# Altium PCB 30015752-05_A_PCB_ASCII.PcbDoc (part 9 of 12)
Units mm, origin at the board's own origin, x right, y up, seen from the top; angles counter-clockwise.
Board outline 100.05 x 72 mm, 10 copper layers (Top, GND_2, Signal_3, Signal_4, PWR_5, GND_6, Signal_7, Signal_8, GND_9, Bottom), stack 1.493 mm thick; 577 components, 546 nets, 2389 pads, 1412 vias.
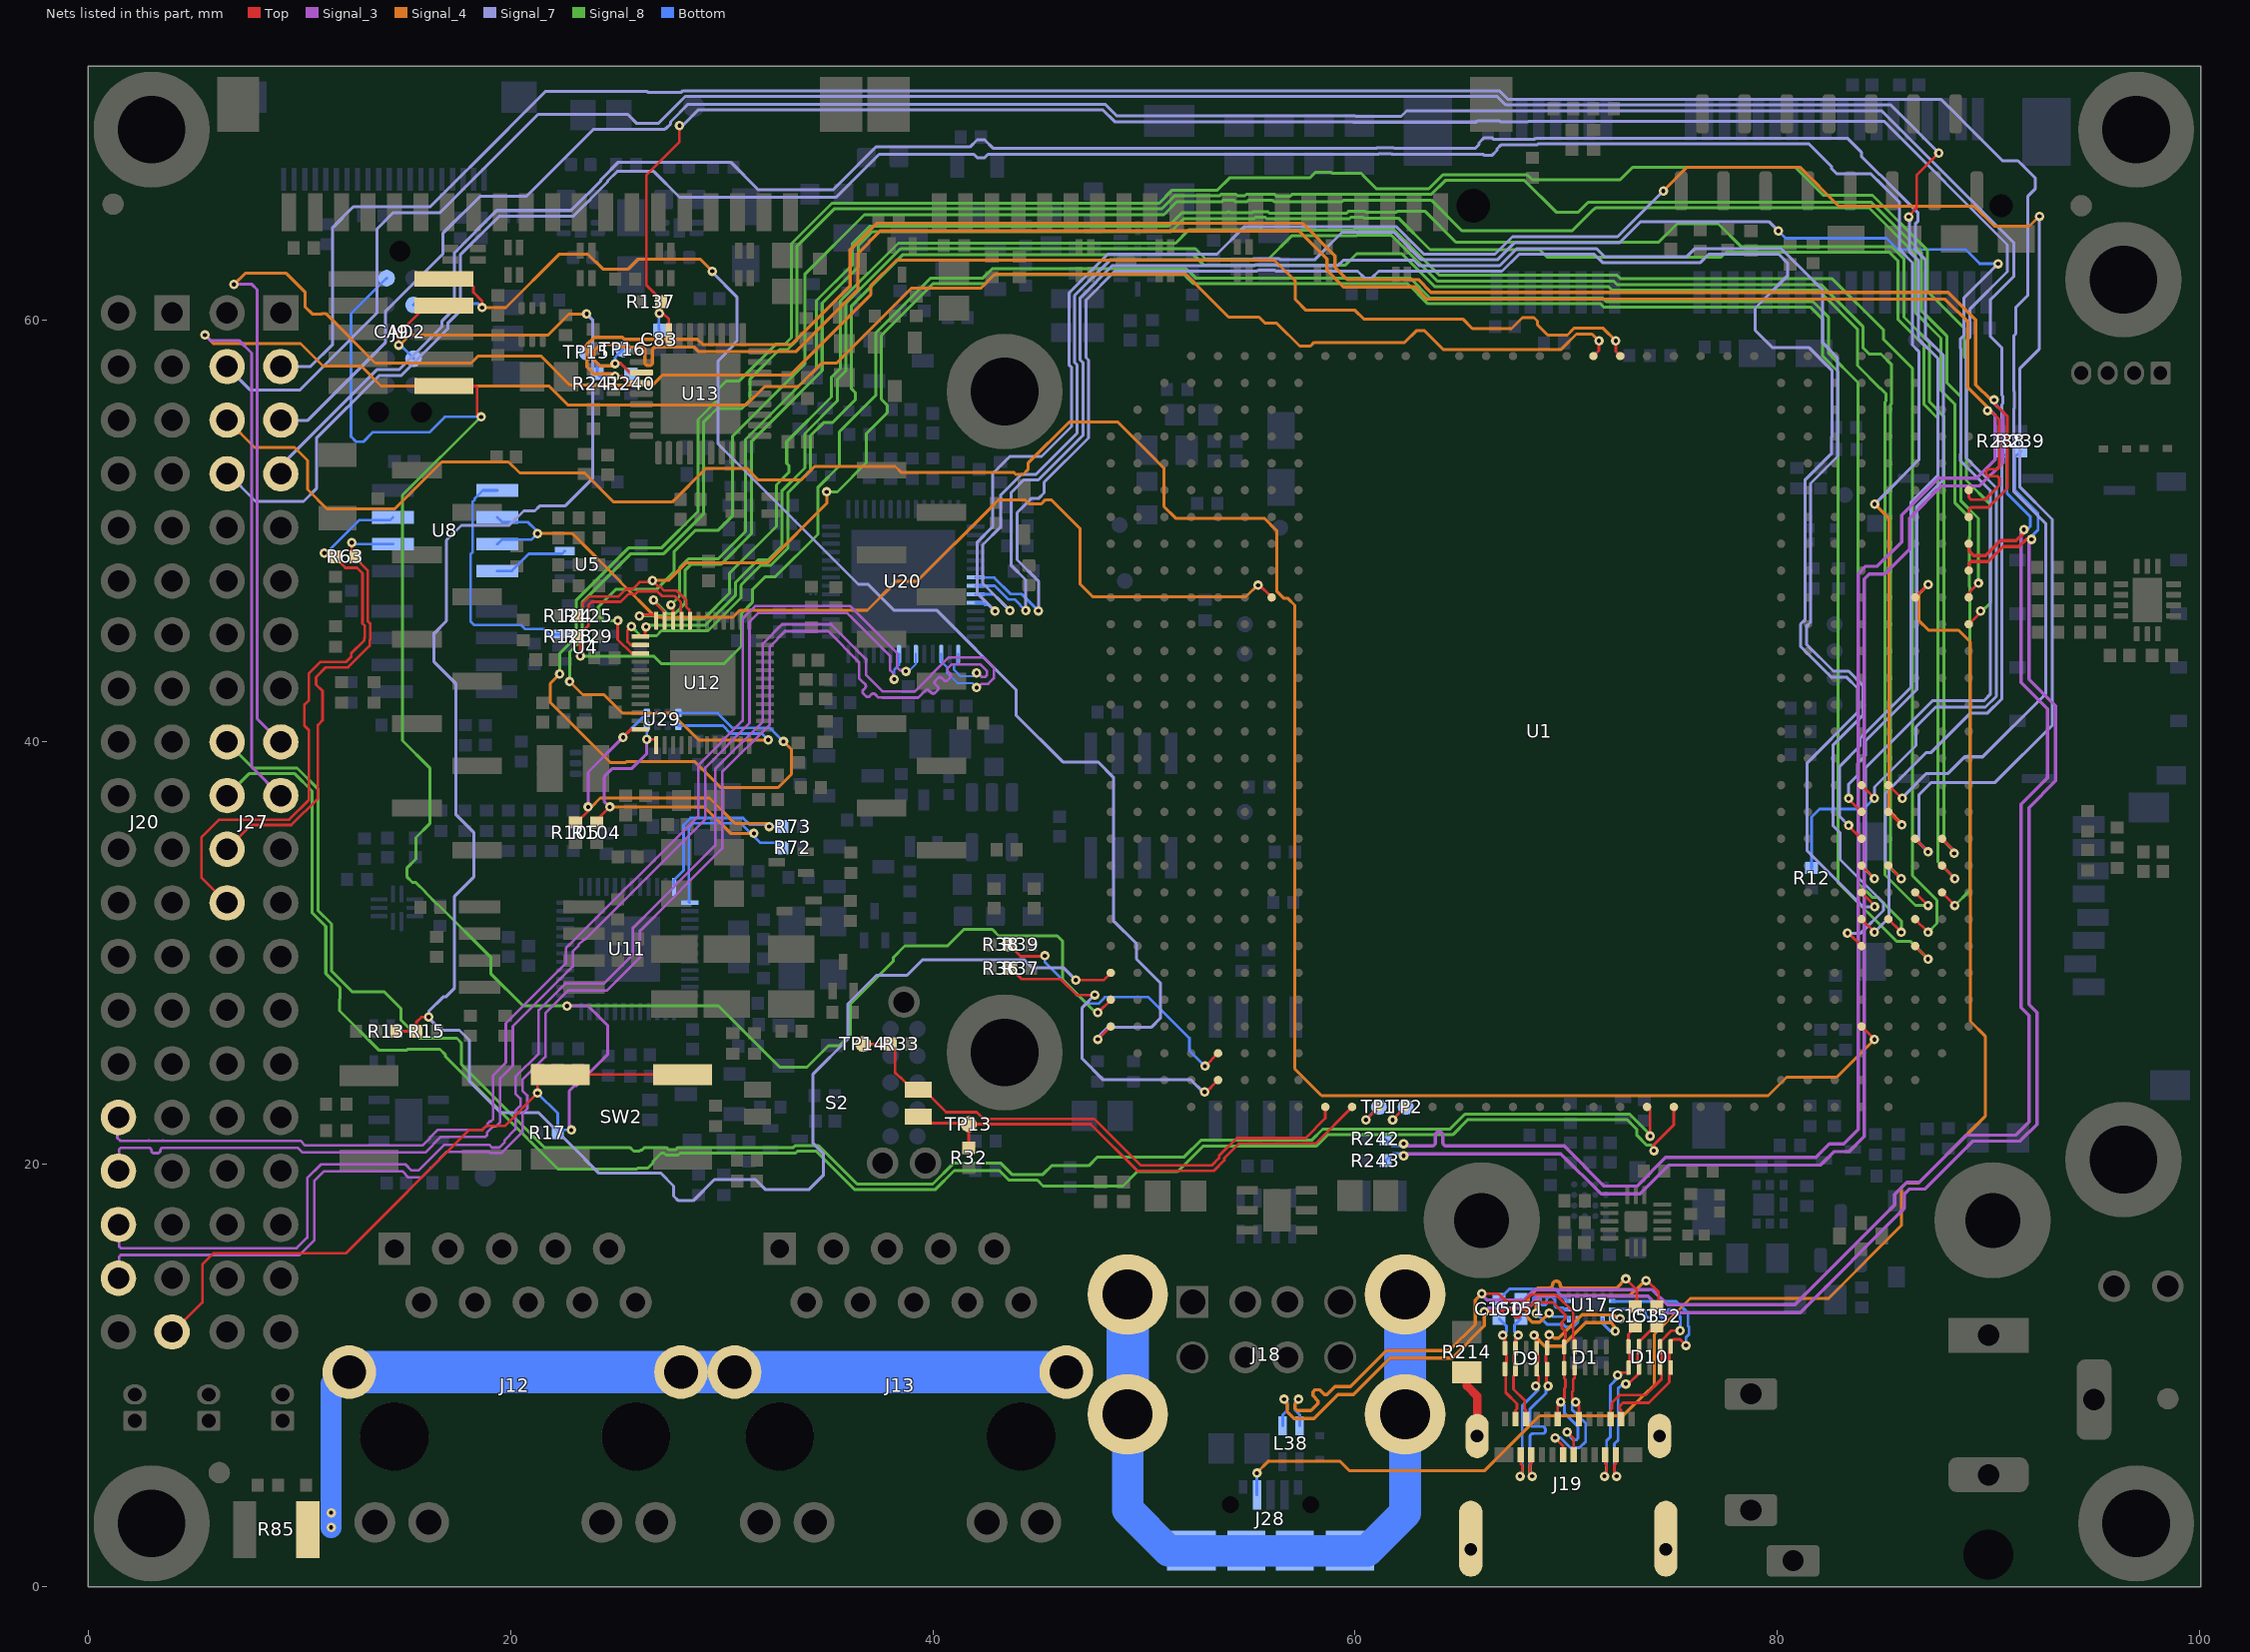
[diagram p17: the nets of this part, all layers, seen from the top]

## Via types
v1: diameter 0.45, hole 0.2, Top to Bottom, tented both sides, 1412 vias

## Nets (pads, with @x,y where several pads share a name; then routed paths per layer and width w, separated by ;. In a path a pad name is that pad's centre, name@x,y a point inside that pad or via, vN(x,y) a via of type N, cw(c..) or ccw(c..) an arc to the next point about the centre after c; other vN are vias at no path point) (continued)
RGMII2_RX_CTL: R124.1 R125.2 U1.C23 U12.32 | length 107
  Top w0.127: R125.2@23.2,46.075 23.275,46.075 23.422,46.221 23.422,46.581 23.74,46.899 25.113,46.899 25.473,47.259 25.797,47.259 26.113,47.575 26.787,47.575 26.968,47.395 27.052,47.395 27.276,47.171 27.876,47.171 28.321,46.726 28.321,46.407 28.464,46.265 28.464,45.786 U12.32@28.5,45.75 ; U1.C23@86.53,30.34 87.14,29.73 v1(87.14,29.72)
  Signal_8 w0.142: v1(34.975,51.85) 35.475,51.85 36.854,53.229 36.854,54.606 37.848,55.6 37.848,55.95 37.562,56.237 37.562,59.261 40.008,61.708 42.487,61.708 42.919,62.14 51.9,62.14 52.332,61.708 62.492,61.708 63.448,60.752 71.625,60.752 71.785,60.592 81.583,60.592 82.15,60.025 82.15,58.275 82.881,57.544 82.881,33.326 85.64,30.567 86.293,30.567 v1(87.14,29.72)
  Signal_4 w0.142: v1(26.726,47.652) 27.473,47.652 28.321,48.5 32.173,48.5 34.975,51.302 v1(34.975,51.85)
RGMII2_RXC: R128.1 R129.2 U1.D22 U12.33 | length 113.2
  Top w0.127: v1(23.3,44.075) 23.3,44.9 R129.2@23.2,45 23.2,45.025 23.685,45.51 23.685,46.485 23.845,46.645 25.218,46.645 25.578,47.005 25.902,47.005 26.037,47.141 26.947,47.141 27.172,46.916 27.772,46.916 28.067,46.621 28.067,45.783 U12.33@28.1,45.75 ; U1.D22@85.26,31.61 85.87,31 v1(85.87,30.99)
  Signal_8 w0.142: v1(23.3,44.075) 26.775,44.075 27.15,43.7 30.1,43.7 30.936,44.536 30.936,46.093 31.452,46.609 31.452,47.212 32.062,47.822 32.536,47.822 34.552,49.837 34.552,52.075 34.575,52.075 35.575,53.075 35.575,54.691 37.292,56.408 37.292,59.372 39.897,61.977 42.375,61.977 42.807,62.409 52.012,62.409 52.443,61.977 62.604,61.977 63.554,61.027 69.176,61.027 69.181,61.022 71.737,61.022 71.897,60.862 81.694,60.862 82.419,60.137 82.419,58.431 83.827,57.023 83.827,33.324 84.52,32.631 84.773,32.631 85.87,31.534 v1(85.87,30.99)
RGMII2_TD0: U1.C22 U12.36 | length 105.6
  Top w0.127: v1(26.1,45.975) 26.15,46.025 26.9,46.025 U12.36@26.9,45.75 ; U1.C22@86.53,31.61 87.14,31 v1(87.14,30.99)
  Signal_8 w0.142: v1(26.1,45.975) 27.144,45.975 27.312,45.808 29.128,45.808 30.375,47.055 30.375,47.999 32.593,50.217 32.593,52.18 33.179,52.766 33.179,53.102 33.079,53.202 33.079,54.225 35.2,56.346 35.2,57.277 35.612,57.688 35.612,60.882 38.36,63.631 51.502,63.631 52.125,64.254 53.761,64.254 55.45,64.254 55.516,64.319 55.529,64.319 55.608,64.24 59.935,64.24 60.016,64.32 60.154,64.32 60.196,64.279 61.825,64.279 64,62.104 72.421,62.104 72.586,61.939 82.611,61.939 85.027,59.523 85.027,59.072 86.4,57.698 86.4,33.672 87.563,32.508 87.563,31.413 v1(87.14,30.99)
RGMII2_TD1: U1.D20 U12.37 | length 101.7
  Top w0.127: U12.37@26.15,45 26.375,45 26.375,45.415 v1(26.42,45.46) ; U1.D20@85.26,34.15 85.87,33.54 v1(85.87,33.53)
  Signal_8 w0.142: v1(26.42,45.46) 26.498,45.538 29.239,45.538 30.644,46.943 30.644,47.546 31.727,48.629 32.202,48.629 32.862,49.29 32.862,51.912 33.937,52.987 33.937,54.617 35.469,56.15 35.469,57.165 35.881,57.577 35.881,60.771 38.472,63.362 52.44,63.362 52.938,62.863 55.888,62.863 56.995,63.97 60.047,63.97 60.078,64.001 61.722,64.001 63.888,61.835 72.231,61.835 72.396,61.669 82.056,61.669 84.066,59.659 84.066,58.659 84.35,58.375 84.911,58.375 85.417,57.869 85.417,56.038 85.369,55.99 85.369,34.031 v1(85.87,33.53)
RGMII2_TD2: U1.C21 U12.38 | length 104.8
  Top w0.127: v1(25.725,45.475) 25.539,45.289 25.539,44.745 25.684,44.6 U12.38@26.15,44.6 ; U1.C21@86.53,32.88 87.14,32.27 v1(87.14,32.26)
  Signal_8 w0.142: v1(25.725,45.475) 26.163,45.037 26.915,45.037 27.148,45.269 29.351,45.269 30.913,46.832 30.913,47.435 31.839,48.36 32.313,48.36 33.132,49.178 33.132,51.801 34.206,52.875 34.206,54.506 34.825,55.125 35.247,55.125 36.325,56.202 36.325,56.553 36.15,56.728 36.15,60.659 38.583,63.092 52.328,63.092 52.827,62.594 59.544,62.594 60.075,63.125 62.217,63.125 63.777,61.565 72.015,61.565 72.181,61.4 81.944,61.4 83.797,59.547 83.797,57.828 84.877,56.748 84.9,56.748 85.148,56.5 85.148,56.15 85.1,56.102 85.1,33.702 86.542,32.26 v1(87.14,32.26)
RGMII2_TD3: U1.B21 U12.39 | length 114.5
  Top w0.127: v1(25.075,45.75) 25.075,44.85 25.725,44.2 U12.39@26.15,44.2 ; U1.B21@87.8,32.88 88.41,32.27 v1(88.41,32.26)
  Signal_8 w0.142: v1(25.075,45.75) 24.4,45.75 24.15,46 24.15,46.4 24.979,47.229 26.902,47.229 27.738,48.066 27.738,49.012 28.742,50.015 29.815,50.015 30.52,50.72 30.52,54.501 33.95,57.931 33.95,62.175 36.752,64.977 50.944,64.977 51.567,65.6 53.701,65.6 53.766,65.665 54.253,65.665 54.319,65.6 54.892,65.6 54.958,65.665 56.086,65.665 56.166,65.586 59.378,65.586 59.459,65.667 63.608,65.667 65.062,64.213 70.283,64.213 71.301,65.232 71.332,65.232 71.4,65.3 84.344,65.3 86.534,63.11 86.534,63.066 86.55,63.05 86.55,60.331 87.752,59.129 87.752,56.656 88.419,55.99 88.419,51.319 89.112,50.625 89.112,49.713 89.102,49.703 89.102,47.35 89.112,47.339 89.112,32.962 v1(88.41,32.26)
RGMII2_TX_CTL: U1.B19 U12.34 | length 104.6
  Top w0.127: v1(27.6,46.5) 27.7,46.4 U12.34@27.7,45.75 ; U1.B19@87.8,35.42 88.41,34.81 88.379,34.779 v1(88.379,34.727)
  Signal_8 w0.142: v1(27.6,46.5) 28.008,46.908 28.008,48.262 28.423,48.677 29.84,48.677 31.132,49.968 31.132,54.336 33.422,56.626 33.422,56.641 34.488,57.708 34.488,60.902 36.2,62.613 36.2,63.625 37.014,64.439 51.167,64.439 51.79,65.061 53.924,65.061 53.989,65.127 54.03,65.127 54.096,65.061 55.116,65.061 55.181,65.127 55.863,65.127 55.943,65.047 59.601,65.047 59.682,65.128 60.489,65.128 60.531,65.086 61.944,65.086 61.986,65.128 63.325,65.128 64.778,63.675 74.378,63.675 75.257,64.553 77.197,64.553 78.281,63.469 85.413,63.469 85.996,62.887 85.996,60.124 87.213,58.906 87.213,56.103 87.88,55.437 87.88,35.33 88.379,34.831 v1(88.379,34.727)
RGMII2_TXC: U1.B20 U12.35 | length 106.5
  Top w0.127: v1(26.775,46.725) 26.775,46.675 27.3,46.15 U12.35@27.3,45.75 ; U1.B20@87.8,34.15 88.41,33.54 v1(88.41,33.53)
  Signal_8 w0.142: v1(26.775,46.725) 27.423,46.077 27.775,46.077 28.277,46.578 28.277,48.15 28.534,48.408 29.952,48.408 31.401,49.857 31.401,54.224 33.691,56.515 33.691,56.53 34.758,57.596 34.758,60.79 36.469,62.502 36.469,63.513 37.125,64.169 51.279,64.169 51.902,64.792 53.984,64.792 55.227,64.792 55.293,64.858 55.752,64.858 55.831,64.778 59.712,64.778 59.793,64.859 60.377,64.859 60.419,64.817 62.048,64.817 63.55,63.315 68.745,63.315 69.092,62.969 77.344,62.969 77.575,63.2 85.301,63.2 85.726,62.775 85.726,60.012 86.944,58.794 86.944,55.992 87.611,55.325 87.611,34.329 v1(88.41,33.53)
RGMII_MDC: U1.A10 U29.5 | length 116.1
  Top w0.127: U1.A10@89.07,46.85 89.07,47.07 v1(89.525,47.525)
  Signal_8 w0.142: v1(22.8,42.86) 22.8,44.275 23.4,44.875 23.4,46.627 25.696,48.923 27.26,48.923 29.15,50.814 29.15,55.169 29.781,55.8 30.95,55.8 31.35,56.2 31.35,57.202 32.731,58.583 33.112,58.583 33.575,59.046 33.575,63.496 35.326,65.246 50.833,65.246 51.455,65.869 53.589,65.869 53.655,65.935 54.365,65.935 54.43,65.869 54.781,65.869 54.847,65.935 56.198,65.935 56.277,65.855 56.93,65.855 57.011,65.936 63.605,65.936 64.269,66.6 68.025,66.6 69.525,65.1 70.575,65.1 71.044,65.569 84.455,65.569 86.819,63.205 86.819,60.442 88.025,59.237 88.025,57.029 88.688,56.366 88.688,51.43 89.525,50.593 v1(89.525,47.525)
  Signal_4 w0.142: v1(22.8,42.86) 23.412,42.248 24.425,42.248 25.3,41.373 27.627,41.373 28.9,40.1 v1(32.2,40.1)
  Bottom w0.127: U29.5@27.95,40.775 30.053,40.775 30.428,40.4 31.9,40.4 v1(32.2,40.1)
RGMII_MDC_3V3: R72.1 R104.1 U11.1 U12.1 U29.8 | length 23.2
  Top w0.127: R104.1@24.075,36.18 24.075,36.3 v1(24.7,36.925) ; v1(26.45,40.125) 26.9,40.125 U12.1@26.9,39.85
  Signal_3 w0.142: v1(24.7,36.925) 24.425,37.2 24.425,38.35 24.825,38.75 25.75,38.75 26.45,39.45 v1(26.45,40.125)
  Signal_4 w0.142: v1(24.7,36.925) 29.175,36.925 30.425,35.675 v1(31.525,35.675)
  Bottom w0.127: v1(26.45,40.125) U29.8@26.45,40.775 ; U11.1@28.49,32.392 28.45,32.432 28.45,35.975 28.625,36.15 30.909,36.15 v1@31.525,35.534 ; v1(31.525,35.675) v1@31.525,35.535 ; R72.1@32.885,34.992 32.885,35.017 32.663,35.239 31.821,35.239 v1@31.525,35.535
RGMII_MDIO: U1.A11 U29.4 | length 125.9
  Top w0.127: U1.A11@89.07,45.58 89.68,46.19 89.668,46.202 v1(89.629,46.202)
  Signal_8 w0.142: v1(22.325,43.225) 22.325,44.2 23.119,44.994 23.119,46.727 25.585,49.192 27.148,49.192 28.881,50.925 28.881,55.281 29.829,56.229 29.829,56.709 30.226,57.106 30.831,57.106 32.577,58.852 33,58.852 33.3,59.152 33.3,63.602 35.214,65.516 50.721,65.516 51.344,66.138 53.478,66.138 54.054,66.715 57.852,66.715 58.121,66.984 58.866,66.984 58.912,66.938 60.287,66.938 60.413,66.812 60.413,66.802 61.01,66.205 63.494,66.205 64.158,66.869 68.152,66.869 68.396,66.625 72.55,66.625 73.148,67.223 80.852,67.223 82.175,65.9 84.505,65.9 87.1,63.305 87.1,61.358 88.85,59.608 88.85,58.25 88.957,58.143 88.957,52.393 90.1,51.25 90.1,46.6 89.702,46.202 v1(89.629,46.202)
  Signal_4 w0.142: v1(22.325,43.225) 21.875,42.775 21.875,41.875 24.723,39.027 25.45,39.027 25.491,39.067 28.737,39.067 29.954,37.85 32.675,37.85 33.298,38.473 33.298,39.652 v1(32.925,40.025)
  Bottom w0.127: U29.4@27.95,41.375 29.812,41.375 30.518,40.669 32.281,40.669 v1(32.925,40.025)
RGMII_MDIO_3V3: R73.1 R105.1 U11.48 U12.48 U29.1 | length 25.1
  Top w0.127: R105.1@23.075,36.18 23.13,36.18 23.675,36.725 v1(23.675,36.925) ; v1(25.327,40.225) v1(25.327,40.225) 25.7,40.6 U12.48@26.15,40.6
  Signal_3 w0.142: v1(23.675,36.925) 23.675,38.575 25.325,40.225 v1(25.327,40.225)
  Signal_4 w0.142: v1(23.675,36.925) 23.825,36.925 24.248,37.348 29.427,37.348 30.625,36.15 32.1,36.15 v1(32.25,36)
  Bottom w0.127: v1(25.327,40.225) 25.327,40.245 25.325,40.247 26.243,41.166 26.29,41.166 26.45,41.325 U29.1@26.45,41.375 ; U11.48@27.74,33.142 27.74,33.462 28.196,33.918 28.196,36.08 28.52,36.404 31.015,36.404 31.328,36.091 32.159,36.091 v1(32.25,36) 32.877,36 R73.1@32.885,35.992
RS485_A: J27.22 R63.1 U8.6 | length 21.7
  Top w0.127: J27.22@6.56,34.92 7.711,36.071 9.612,36.071 10.871,37.33 10.871,40.808 11.091,41.028 11.091,42.422 10.784,42.728 10.784,43.072 11.249,43.536 12.299,43.536 13.328,44.565 13.328,44.822 13.349,44.842 13.349,45.608 13.242,45.714 13.242,48.108 12.475,48.875 v1(12.475,49.45)
  Bottom w0.127: v1(12.475,49.45) 12.55,49.375 U8.6@14.43,49.375
RS485_B: J27.24 R63.2 U8.7 | length 28.6
  Top w0.127: J27.24@6.56,32.38 5.354,33.586 5.354,35.479 6.2,36.325 9.507,36.325 10.445,37.262 10.445,40.557 10.235,40.766 10.235,41.774 10.446,41.985 10.446,43.255 10.981,43.79 12.194,43.79 12.454,44.051 12.454,44.205 13.074,44.825 13.074,44.927 13.095,44.948 13.095,45.502 12.988,45.609 12.988,47.987 12.725,48.25 12.175,48.25 R63.2@11.695,48.73 ; v1(11.176,48.952) 11.473,48.952 R63.2@11.695,48.73 ; R63.2@11.695,48.775 R63.2@11.695,48.73 ; R63.2@11.825,48.525 11.695,48.655 R63.2@11.695,48.73
  Bottom w0.127: v1(11.176,48.952) 11.277,48.952 12.83,50.505 14.29,50.505 U8.7@14.43,50.645
RS485_RE#/DE: U1.AG10 U8.2 U8.3 | length 47.3
  Top w0.127: v1(55.403,47.427) 55.407,47.427 55.44,47.46 U1.AG10@56.05,46.85
  Signal_4 w0.142: v1(21.275,49.875) 22.928,49.875 25.217,47.587 25.217,47.565 26.862,45.92 30.54,45.92 30.86,46.24 36.9,46.24 38.28,47.62 39.268,47.62 42.723,51.075 42.723,51.083 43.115,51.475 44.366,51.475 44.563,51.278 45.137,51.278 45.334,51.475 45.6,51.475 46.98,50.095 46.98,47.47 47.575,46.875 54.829,46.875 55.403,47.449 v1(55.403,47.427)
  Bottom w0.127: U8.3@19.37,49.375 19.579,49.584 20.978,49.584 21.268,49.875 v1(21.275,49.875) 21.213,49.937 21.213,50.024 20.822,50.415 19.599,50.415 U8.2@19.37,50.645
SAI0_RXD: U1.E21 U20.7 | length 94.7
  Top w0.127: U1.E21@83.99,32.88 84.604,32.266 v1(84.604,32.202)
  Signal_7 w0.142: v1(45,46.213) 45,47.62 43.991,48.629 43.991,50.863 44.675,51.547 45.025,51.547 45.273,51.795 45.273,52.304 47.375,54.406 47.375,58.087 47.254,58.207 47.254,60.929 48.623,62.298 55.354,62.298 55.406,62.35 56.194,62.35 56.246,62.298 60.129,62.298 60.45,61.977 60.8,61.977 61.12,62.297 66.964,62.297 67.765,63.098 71.331,63.098 71.719,62.71 76.36,62.71 76.753,63.103 80.07,63.103 80.5,62.673 80.5,62.1 78.95,60.55 78.95,59.5 79.775,58.675 81.512,58.675 82.587,57.6 82.587,54.473 82.58,54.467 82.58,53.68 81.306,52.406 81.306,45.784 81.108,45.587 81.108,44.522 82.547,43.083 83.272,43.083 83.802,42.552 83.802,41.401 81.4,38.999 81.4,34.862 84.06,32.202 v1(84.604,32.202)
  Bottom w0.127: U20.7@42.03,47.8 42.045,47.784 42.903,47.784 43.678,47.009 44.203,47.009 v1(45,46.213)
SAI0_TXC: U1.E23 U20.8 | length 93.8
  Top w0.127: v1(83.325,30.95) 83.38,30.95 U1.E23@83.99,30.34
  Signal_7 w0.142: v1(44.4,46.225) 44.4,47.68 43.722,48.358 43.722,51.821 44.311,52.41 44.999,52.41 47.106,54.517 47.106,57.975 46.985,58.096 46.985,61.041 48.512,62.567 55.243,62.567 55.295,62.619 56.305,62.619 56.357,62.567 59.189,62.567 59.447,62.825 62.776,62.825 63.035,62.566 66.853,62.566 67.654,63.367 71.442,63.367 71.831,62.979 75.704,62.979 76.097,63.372 80.182,63.372 82.15,61.404 82.15,58.902 82.856,58.196 82.856,54.362 82.849,54.355 82.849,53.524 81.575,52.25 81.575,45.672 81.378,45.475 81.378,44.633 82.659,43.352 83.383,43.352 84.071,42.664 84.071,41.289 82.65,39.868 82.65,36.027 82.969,35.708 82.969,34.435 85.027,32.377 85.027,32.026 83.951,30.95 v1(83.325,30.95)
  Bottom w0.127: U20.8@42.03,47.4 42.928,47.4 43.573,46.755 43.87,46.755 v1(44.4,46.225)
SAI0_TXD: U1.E20 U20.9 | length 102.2
  Top w0.127: U1.E20@83.99,34.15 84.6,33.54 v1(84.6,33.53)
  Signal_7 w0.142: v1(43.65,46.225) 42.36,47.515 42.36,49.34 43.22,50.2 43.22,51.7 44.2,52.679 44.887,52.679 46.837,54.629 46.837,57.864 46.716,57.984 46.716,61.152 48.4,62.837 55.131,62.837 55.183,62.889 56.417,62.889 56.469,62.837 58.084,62.837 59.396,64.148 61.833,64.148 63.146,62.835 66.741,62.835 67.565,63.66 72.54,63.66 73.521,64.64 79.167,64.64 79.179,64.651 79.6,64.651 v1(80.051,64.201) ; v1(84.6,33.53) 84.177,33.953 84.177,38.785 87.346,41.954 89.78,41.954 90.102,42.277 90.102,51.894 88.681,53.315 88.681,53.654 88.688,53.662 88.688,58.628 88.681,58.636 88.681,59.102 88.843,59.265 88.843,61.043 90.453,62.653 v1(90.454,62.653)
  Bottom w0.127: U20.9@42.03,47 42.875,47 v1(43.65,46.225) ; v1(80.051,64.201) 80.392,63.859 85.166,63.859 85.694,63.331 88.906,63.331 89.585,62.653 v1(90.454,62.653)
SAI0_TXFS: U1.C19 U20.10 | length 106.8
  Top w0.127: U1.C19@86.53,35.42 87.14,34.81 v1(87.14,34.8)
  Signal_4 w0.142: v1(74.6,66.1) 75.726,67.226 81.067,67.226 82.918,65.375 89.325,65.375 90.275,64.425 91.932,64.425 92.407,64.9 v1(92.425,64.9)
  Signal_7 w0.142: v1(42.95,46.2) 42.091,47.059 42.091,49.452 42.84,50.201 42.84,52.715 43.651,53.526 44.277,53.526 ; 44.278,53.525 45.15,53.525 46.567,54.942 46.567,57.752 46.446,57.873 46.446,61.264 48.289,63.106 53.45,63.106 54.762,64.417 61.945,64.417 63.258,63.105 66.629,63.105 67.454,63.929 72.429,63.929 v1(74.6,66.1) ; v1(87.14,34.8) 86.708,35.232 86.708,37.507 87.275,38.073 90.298,38.073 93.02,40.795 93.02,50.55 91.475,52.095 91.475,55.674 91.495,55.694 91.495,56.714 91.475,56.733 91.475,57.675 92.4,58.6 92.4,64.875 v1(92.425,64.9)
  Bottom w0.127: U20.10@42.03,46.6 42.36,46.6 42.469,46.49 42.653,46.49 42.943,46.2 v1(42.95,46.2)
SCU_BOOT_MODE0: R33.2 S2.2 TP14.1 U1.AE29 | length 26.5
  Top w0.127: TP14.1@36.7,25.7 R33.2@38.02,25.7 38.209,25.511 38.209,24.353 38.46,24.102 38.488,24.102 39.055,23.535 S2.2@39.31,23.535 39.565,23.535 40.629,22.471 42.07,22.471 42.388,22.154 47.646,22.154 49.854,19.946 53.205,19.946 53.555,20.296 53.555,20.402 54.399,21.246 57.659,21.246 58.59,22.177 U1.AE29@58.59,22.72
SCU_BOOT_MODE1: R32.1 S2.1 TP13.1 U1.AD29 | length 24.1
  Top w0.127: S2.1@39.31,22.265 39.626,21.949 41.651,21.949 TP13.1@41.7,21.9 ; R32.1@41.7,20.78 TP13.1@41.7,21.9 ; U1.AD29@59.86,22.72 58.132,20.992 54.504,20.992 53.809,20.297 53.809,20.191 53.31,19.692 49.685,19.692 47.477,21.9 TP13.1@41.7,21.9
SCU_BOOT_MODE2: R36.2 R37.2 U1.AJ28 | length 15.2
  Top w0.127: R37.2@43.7,29.275 44.2,28.775 46.05,28.775 46.8,28.025 v1(47.675,28.025) ; v1(52.878,23.426) 52.878,23.358 U1.AJ28@53.51,23.99
  Signal_7 w0.142: v1(47.675,28.025) 47.075,27.425 47.075,25 48.075,24 52.225,24 52.799,23.426 v1(52.878,23.426)
SCU_BOOT_MODE3: R38.2 R39.2 U1.AJ27 | length 13.3
  Top w0.127: R38.2@43.7,30.4 43.7,30.3 44.15,29.85 45.276,29.85 v1(45.302,29.876) ; v1(52.89,24.65) 52.9,24.65 U1.AJ27@53.51,25.26
  Bottom w0.127: v1(45.302,29.876) 45.302,29.602 45.3,29.6 47.29,27.61 47.847,27.61 48.156,27.918 50.21,27.918 52.15,25.978 52.15,25.39 v1(52.89,24.65)
SCU_UART_RX: TP1.1 U1.AC29 | length 1.7
  Top w0.127: v1(60.51,22.11) 60.52,22.11 U1.AC29@61.13,22.72
  Bottom w0.127: v1(60.51,22.11) 60.515,22.11 61.125,22.72 TP1.1@61.13,22.72
SCU_UART_TX: TP2.1 U1.AB29 | length 1.7
  Top w0.127: v1(61.78,22.11) 61.79,22.11 U1.AB29@62.4,22.72
  Bottom w0.127: v1(61.78,22.11) 61.785,22.11 62.395,22.72 TP2.1@62.4,22.72
SHLD: J12.SHLD1 J12.SHLD2 J13.SHLD1 J13.SHLD2 J18.SH1 J18.SH2 J18.SH3 J18.SH4 J28.6 J28.7 J28.8 J28.9 R85.2 | length 77.1
  Bottom w1: v1(11.5,2.8) v1(11.5,3.5) 11.5,9.6 11.85,9.95 11.85,10.163 J12.SHLD1@12.361,10.163 J12.SHLD1@12.469,10.163
  Bottom w1.5: J18.SH1@49.231,8.155 49.231,3.644 51.175,1.7 J28.9@52.25,1.7 J28.8@54.85,1.7 J28.7@57.15,1.7 J28.6@59.75,1.7 60.575,1.7 62.371,3.496 J18.SH3@62.371,8.155
  Bottom w2: J12.SHLD1@12.469,10.163 J12.SHLD2@28.071,10.163 J13.SHLD1@30.611,10.163 J13.SHLD2@46.213,10.163 ; J18.SH1@49.231,8.155 J18.SH2@49.231,13.835 ; J18.SH3@62.371,8.155 J18.SH4@62.371,13.835
SPI0_CS0: J27.4 U1.E19 | length 127.2
  Top w0.127: v1(83.379,36.052) 83.362,36.052 83.36,36.05 U1.E19@83.99,35.42 ; v1(86.229,64.878) 86.229,64.929 86.6,65.3 86.6,66.85 v1(87.65,67.9)
  Signal_7 w0.142: J27.4@6.56,57.78 7.658,56.682 10.032,56.682 13.675,60.325 13.675,64.3 14.45,65.075 16.654,65.075 21.302,69.723 25.552,69.723 25.983,69.292 26.992,69.292 28.277,70.577 66.733,70.577 67.143,70.167 85.383,70.167 v1(87.65,67.9) ; v1(83.379,36.052) 82.956,36.475 82.956,38.855 83.908,39.807 83.908,40.167 86.333,42.592 86.333,51.375 87.604,52.646 87.604,54.1 87.606,54.102 87.606,58.169 86.675,59.1 86.675,62.806 86.268,63.213 86.268,64.651 86.33,64.714 86.33,64.777 v1(86.229,64.878)
SPI0_CS1: J27.6 U1.E26 | length 115.6
  Top w0.127: U1.E26@83.99,26.53 84.6,25.92 v1(84.6,25.91)
  Signal_4 w0.142: J27.6@6.56,55.24 J27.6@6.585,55.24 ; J27.6@6.575,55.245 6.58,55.245 J27.6@6.585,55.24 ; v1(84.6,25.91) 82.815,24.125 80.445,24.125 79.569,23.249 58.418,23.249 58.374,23.292 57.145,24.521 57.145,46.48 56.825,46.8 56.635,46.8 56.287,47.148 56.287,50.013 55.7,50.6 51.5,50.6 50.95,51.15 50.95,52.975 48.775,55.15 46.45,55.15 44.525,53.225 44.525,52.927 44.277,52.679 43.927,52.679 43.831,52.775 38.5,52.775 38.225,53.05 34.4,53.05 33.754,52.404 31.746,52.404 31.183,52.967 29.261,52.967 27.658,51.363 24.879,51.363 23.5,52.742 20.433,52.742 19.904,53.271 16.736,53.271 14.5,51.035 11.311,51.035 10.386,51.96 10.386,53.339 9.775,53.95 7.875,53.95 J27.6@6.585,55.24
SPI0_IRQ_N: J27.8 U1.D18 | length 124.5
  Top w0.127: v1@84.6,51.27 v1(84.61,51.27) ; U1.D18@85.26,36.69 85.875,36.075 85.877,36.077 v1(85.904,36.077)
  Signal_4 w0.142: v1(84.61,51.27) 85.3,50.58 85.3,36.75 85.904,36.146 v1(85.904,36.077)
  Signal_7 w0.142: J27.8@6.575,52.705 6.62,52.705 7.925,51.4 10.2,51.4 10.802,52.002 10.802,54.39 13.773,57.362 14.823,57.362 17.023,59.562 17.023,59.833 17.613,60.423 17.613,63.069 19.45,64.906 22.977,64.906 24.604,66.533 24.604,66.579 25.048,67.023 26.787,67.023 28.007,65.803 35.418,65.803 37.456,67.84 41.942,67.84 42.102,67.68 42.452,67.68 42.612,67.84 61.111,67.84 61.141,67.871 61.715,67.871 61.757,67.829 66.073,67.829 66.125,67.777 66.475,67.777 66.723,68.025 66.723,68.098 66.904,68.279 68.618,68.279 68.67,68.331 81.494,68.331 82.581,67.244 82.581,67.153 82.829,66.905 84.436,66.905 84.746,66.594 84.758,66.594 85.794,65.558 85.794,63.306 86.4,62.7 86.4,58.8 86.7,58.5 86.7,53.36 v1(84.61,51.27)
SPI0_SCK: J27.3 U1.D17 | length 128.9
  Top w0.127: U1.D17@85.26,37.96 85.88,37.34 v1(85.922,37.34)
  Signal_7 w0.142: J27.3@9.1,57.78 10.52,57.78 11.575,58.835 11.575,64.375 12.555,65.355 16.195,65.355 17.917,67.077 17.925,67.077 18.173,67.325 18.173,67.333 21.663,70.823 26.45,70.823 26.498,70.775 28.094,70.775 28.165,70.846 66.844,70.846 67.254,70.436 87.759,70.436 90.666,67.529 91.402,67.529 92.231,66.7 92.231,66.216 91.875,65.86 91.875,61.166 91.3,60.591 91.3,59.335 91.206,59.24 91.206,56.622 91.225,56.602 91.225,55.805 91.206,55.786 91.206,51.855 92.711,50.35 92.711,42.286 89.725,39.3 88.875,39.3 88.089,38.514 87.061,38.514 85.886,37.34 v1(85.922,37.34)
SPI0_SDI: J27.5 U1.E22 | length 130.2
  Top w0.127: U1.E22@83.99,31.61 84.6,31 v1(84.6,30.995)
  Signal_7 w0.142: J27.5@9.1,55.24 10.396,55.24 14.065,58.91 14.065,60.385 16.806,63.125 16.806,64.106 18.55,65.85 20.75,65.85 23.923,69.023 27.3,69.023 27.325,69.048 27.352,69.048 27.577,69.273 27.577,69.375 28.411,70.21 48.162,70.21 48.723,69.648 60.01,69.648 60.028,69.63 62.18,69.63 62.447,69.897 84.941,69.897 91.2,63.639 91.2,62.05 90.1,60.95 90.1,59.2 90.641,58.659 90.641,56.425 90.687,56.379 90.687,56.029 90.641,55.983 90.641,42.054 89.962,41.375 89.16,41.375 87.294,39.509 87.06,39.509 85.125,37.574 85.125,34.3 85.296,34.129 85.296,31.691 v1(84.6,30.995)
SPI0_SDO: J27.7 U1.E18 | length 120.3
  Top w0.127: v1(83.379,37.327) 83.357,37.327 83.355,37.325 U1.E18@83.99,36.69
  Signal_7 w0.142: J27.7@9.115,52.705 9.115,53.084 13.662,57.631 14.712,57.631 16.754,59.673 16.754,59.944 17.344,60.535 17.344,63.181 19.338,65.175 22.865,65.175 24.275,66.585 24.275,66.625 24.335,66.685 24.335,66.69 25.108,67.463 30.425,67.463 31.738,66.15 35.271,66.15 37.3,68.179 41.754,68.179 42.102,68.526 42.452,68.526 42.852,68.127 61.017,68.127 61.03,68.14 61.826,68.14 61.839,68.127 65.702,68.127 65.877,68.302 65.877,68.375 66.125,68.623 66.475,68.623 66.547,68.551 68.51,68.551 68.559,68.6 83.32,68.6 83.98,67.94 83.98,67.742 84.858,66.864 84.869,66.864 86.652,65.081 86.652,64.655 86.537,64.54 86.537,63.325 87.025,62.837 87.025,59.15 87.875,58.299 87.875,53.99 87.873,53.988 87.873,52.423 86.602,51.152 86.602,42.481 84.177,40.055 84.177,39.357 83.802,38.982 83.802,38.427 83.379,38.004 v1(83.379,37.327)
SPKL_N: J20.34 U20.22 | length 58.9
  Signal_3 w0.124: J20.34@1.46,19.68 1.46,19.685 1.46,20.712 1.533,20.785 2.35,20.785 2.562,20.785 2.859,20.785 cw(c2.859,20.658) 2.987,20.658 ccw(c3.114,20.658) 3.114,20.53 3.284,20.53 ccw(c3.284,20.658) 3.411,20.658 cw(c3.538,20.658) 3.538,20.785 3.55,20.785 9.915,20.785 10.138,20.562 15.962,20.562 16.706,21.306 18.808,21.306 18.886,21.383 18.886,21.494 19.166,21.774 19.166,21.789 19.292,21.789 19.505,22.002 19.505,24.08 20.105,24.68 20.105,26.53 22.95,29.375 22.95,30.083 23.211,30.344 23.211,30.397 23.453,30.639 23.506,30.639 29.225,36.358 29.225,38.8 31.319,40.894 31.319,45.699 31.739,46.119 35.931,46.119 37.975,44.075 37.975,43.404 38.123,43.256 38.123,43.027 v1(38.175,42.975)
  Bottom w0.102: v1(38.175,42.975) 38.175,43.425 38.4,43.65 U20.22@38.4,44.17
SPKL_P: J20.32 U20.20 | length 58.9
  Signal_3 w0.124: J20.32@1.46,22.22 1.445,22.205 1.375,22.135 1.375,21.25 1.51,21.115 2.795,21.115 2.853,21.115 2.859,21.122 2.859,21.124 2.868,21.116 2.873,21.121 2.878,21.115 2.882,21.115 2.886,21.119 2.889,21.115 2.981,21.115 3.417,21.115 3.509,21.115 3.512,21.119 3.515,21.115 3.52,21.115 3.525,21.121 3.53,21.116 3.538,21.124 3.538,21.122 3.545,21.115 3.602,21.115 ; 3.603,21.115 10.052,21.115 10.275,20.892 15.817,20.892 16.561,21.636 18.672,21.636 18.914,21.878 18.914,21.931 19.024,22.041 19.077,22.041 19.175,22.139 19.175,24.217 19.775,24.817 19.775,26.675 22.62,29.52 22.62,30.22 28.895,36.495 28.895,38.92 30.989,41.014 30.989,45.836 31.602,46.449 36.076,46.449 38.305,44.22 38.305,43.541 38.444,43.402 38.673,43.402 v1(38.725,43.35)
  Bottom w0.102: v1(38.725,43.35) 38.85,43.35 39.2,43.7 U20.20@39.2,44.17
SPKR_N: J20.38 U20.15 | length 71.3
  Signal_3 w0.124: J20.38@1.46,14.6 1.46,14.605 1.46,15.632 1.533,15.705 10.005,15.705 10.7,16.4 10.7,19.201 11.168,19.67 14.877,19.67 15.167,19.381 15.783,19.381 16.219,19.817 16.219,19.834 16.98,20.595 18.966,20.595 19.019,20.541 19.571,20.541 19.625,20.595 19.637,20.595 20.563,21.521 20.563,22.41 20.794,22.642 20.794,23.258 20.563,23.49 20.563,24.013 21.65,25.1 21.65,27.158 22.717,28.225 24.549,28.225 26.13,29.807 26.13,31.063 30.025,34.958 30.025,38.575 32.275,40.825 32.275,44.525 33,45.25 35.044,45.25 36.506,43.788 36.506,43.027 36.739,42.794 36.793,42.74 cw(c36.703,42.65) 36.793,42.56 36.707,42.474 ccw(c36.797,42.384) 36.707,42.294 36.827,42.174 ccw(c36.917,42.264) 37.007,42.174 37.093,42.26 cw(c37.183,42.17) 37.273,42.26 37.333,42.2 37.419,42.114 37.612,42.114 37.626,42.1 39.308,42.1 39.55,42.342 39.643,42.434 cw(c39.733,42.344) 39.823,42.434 39.926,42.332 ccw(c40.016,42.422) 40.106,42.332 40.226,42.452 ccw(c40.136,42.542) 40.226,42.632 40.123,42.735 cw(c40.213,42.825) 40.123,42.915 40.243,43.035 cw(c40.333,42.945) 40.423,43.035 40.526,42.932 ccw(c40.616,43.022) 40.706,42.932 40.826,43.052 ccw(c40.736,43.142) 40.826,43.232 40.723,43.335 cw(c40.813,43.425) 40.723,43.515 40.783,43.575 40.891,43.683 42.247,43.683 42.555,43.374 42.555,43.163 42.482,43.09 42.311,43.09 42.132,43.269 v1(42.075,43.269)
  Bottom w0.102: U20.15@41.2,44.17 41.2,43.8 41,43.6 41,43.425 41.3,43.125 41.932,43.125 v1(42.075,43.269)
SPKR_P: J20.36 U20.17 | length 71.5
  Signal_3 w0.124: J20.36@1.46,17.14 1.46,16.108 1.533,16.035 9.868,16.035 10.37,16.537 10.37,19.338 11.032,20 15.014,20 15.303,19.711 15.647,19.711 16.861,20.925 18.991,20.925 19.124,20.792 19.467,20.792 19.709,21.035 19.709,21.134 20.233,21.658 20.233,22.547 20.464,22.778 20.464,23.122 20.233,23.353 20.233,24.15 21.325,25.242 21.325,27.3 22.58,28.555 24.412,28.555 25.8,29.943 25.8,31.2 29.695,35.095 29.695,38.712 31.945,40.962 31.945,44.662 32.863,45.58 35.181,45.58 36.837,43.925 36.837,43.183 37.628,42.392 39.134,42.392 40.754,44.013 42.383,44.013 42.886,43.511 42.886,43.026 42.619,42.76 42.311,42.76 42.132,42.582 v1(42.075,42.582)
  Bottom w0.102: U20.17@40.4,44.17 40.4,43.818 40.575,43.643 40.67,43.548 40.67,43.288 41.163,42.795 41.862,42.795 v1(42.075,42.582)
SS3_1_RX_N: D9.1 D9.10 J19.B10 U17.1 | length 14
  Top w0.132: J19.B10@68.35,6.24 68.35,5.824 68.284,5.758 68.284,5.329 v1(68.389,5.225) ; D9.1@69.1,11.3 69.056,11.256 69.056,10.963 69.034,10.941 69.034,10.661 69.056,10.639 69.056,10.3 69.056,10.099 69.1,10.055 69.068,10.023 69.068,9.736 69.078,9.727 69.078,9.561 v1(69.139,9.5) ; D9.1@69.1,11.305 69.144,11.349 69.144,11.869 v1(69.2,11.925)
  Signal_4 w0.157: v1(69.2,11.925) 69.276,11.925 69.439,11.763 69.647,11.763 70.758,12.874 71.456,12.874 71.464,12.866 72.269,12.866 72.405,12.731 72.55,12.731 72.594,12.731 72.563,12.7 v1(72.55,12.7)
  Bottom w0.132: v1(68.389,5.225) 68.284,5.329 68.284,6.75 68.284,6.916 68.284,7.099 cw(c68.434,7.099) 68.434,7.248 68.874,7.248 ccw(c68.874,7.398) 69.024,7.398 69.024,7.431 ccw(c68.874,7.431) 68.874,7.58 68.434,7.58 cw(c68.434,7.73) 68.284,7.73 68.284,7.775 68.284,8.409 69.034,9.159 69.034,9.31 69.139,9.414 v1(69.139,9.5) ; U17.1@72.125,12.675 72.15,12.7 v1(72.55,12.7)
SS3_1_RX_P: D9.2 D9.9 J19.B11 U17.2 | length 14.1
  Top w0.132: v1(67.812,5.225) 67.916,5.329 67.916,5.758 67.85,5.824 J19.B11@67.85,6.24 ; v1(68.475,11.9) 68.6,11.775 D9.2@68.6,11.3 68.6,11.055 68.605,11.055 68.644,11.016 68.644,10.961 68.666,10.939 68.666,10.661 68.644,10.639 68.644,10.584 68.605,10.545 68.6,10.545 D9.9@68.6,10.3 68.6,10.06 68.7,9.96 68.7,9.725 68.562,9.586 v1(68.562,9.5)
  Signal_4 w0.157: v1(68.475,11.9) 68.98,11.395 69.8,11.395 70.911,12.506 71.303,12.506 71.311,12.498 72.117,12.498 72.269,12.346 72.269,12.156 v1(72.325,12.1)
  Bottom w0.132: v1@67.808,5.221 v1(67.812,5.225) 67.916,5.329 67.916,8.562 68.665,9.311 68.562,9.414 v1(68.562,9.5) ; U17.2@71.725,12.675 71.725,12.475 72.1,12.1 v1(72.325,12.1)
SS3_1_TX_N: C151.2 D9.4 D9.7 J19.A3 | length 5.4
  Top w0.132: v1(67.725,11.9) 67.6,11.775 D9.4@67.6,11.3 67.6,11.055 67.595,11.055 67.556,11.016 67.556,10.961 67.534,10.939 67.534,10.661 67.556,10.639 67.556,10.584 67.595,10.545 67.6,10.545 D9.7@67.6,10.3 67.6,10.06 67.507,9.967 67.507,9.343 68.034,8.816 68.034,8.422 68.1,8.356 J19.A3@68.1,7.94
  Bottom w0.132: v1@67.725,11.958 v1(67.725,11.9) 67.547,12.078 67.547,12.387 C151.2@67.85,12.69
SS3_1_TX_P: C150.2 D9.5 D9.6 J19.A2 | length 5.4
  Top w0.132: v1(67,11.9) 67.1,11.8 D9.5@67.1,11.3 67.1,11.055 67.105,11.055 67.144,11.016 67.144,10.961 67.166,10.939 67.166,10.661 67.144,10.639 67.144,10.584 67.105,10.545 67.1,10.545 67.139,10.507 67.139,9.19 67.666,8.663 67.666,8.422 67.6,8.356 J19.A2@67.6,7.94
  Bottom w0.132: C150.2@66.825,12.69 67.178,12.337 67.178,12.078 v1(67,11.9) v1@67,11.958
SS3_2_RX_N: D10.4 D10.7 J19.A10 U17.16 | length 11.8
  Top w0.132: J19.A10@72.1,7.94 72.1,8.356 72.166,8.422 72.166,8.703 72.532,9.068 73.752,9.068 74.516,9.832 74.516,10.014 74.494,10.036 74.494,10.375 74.494,10.576 74.45,10.62 74.455,10.62 74.494,10.659 74.494,10.714 74.516,10.736 74.516,11.014 74.494,11.036 74.494,11.091 74.455,11.13 74.45,11.13 74.494,11.174 D10.7@74.494,11.375 ; D10.7@74.45,11.375 74.45,11.6 74.975,12.125 v1(75.4,12.125)
  Bottom w0.132: U17.16@72.175,13.125 U17.16@72.191,13.141 ; U17.16@72.192,13.141 72.196,13.136 72.95,13.136 73.613,13.136 cw(c73.613,12.987) 73.763,12.987 73.763,12.892 ccw(c73.912,12.892) 73.912,12.743 73.945,12.743 ccw(c73.945,12.892) 74.095,12.892 74.095,12.987 cw(c74.244,12.987) 74.244,13.136 74.277,13.136 cw(c74.277,12.987) 74.427,12.987 74.427,12.892 ccw(c74.576,12.892) 74.576,12.743 74.61,12.743 ccw(c74.61,12.892) 74.759,12.892 74.759,12.987 cw(c74.908,12.987) 74.908,13.136 74.925,13.136 75.064,13.136 75.4,12.8 v1(75.4,12.125)
SS3_2_RX_P: D10.5 D10.6 J19.A11 U17.15 | length 11.8
  Top w0.132: J19.A11@72.6,7.94 72.6,8.356 72.534,8.422 72.534,8.55 72.684,8.7 73.905,8.7 74.884,9.679 74.884,10.014 74.906,10.036 74.906,10.375 74.906,10.576 74.95,10.62 74.945,10.62 74.906,10.659 74.906,10.714 74.884,10.736 74.884,11.014 74.906,11.036 D10.6@74.906,11.375 ; D10.6@74.95,11.375 74.95,11.579 75.078,11.707 75.393,11.707 v1(75.675,11.425)
  Bottom w0.132: U17.15@72.175,13.525 72.191,13.509 72.344,13.509 72.349,13.505 74.578,13.505 74.583,13.509 74.912,13.509 74.916,13.505 75.216,13.505 75.768,12.953 75.768,12.348 75.818,12.298 75.818,11.952 75.675,11.809 v1(75.675,11.425)
SS3_2_TX_N: C153.2 D10.1 D10.10 J19.B3 | length 9.1
  Top w0.132: v1(71.811,5.225) 71.916,5.329 71.916,5.758 71.85,5.824 J19.B3@71.85,6.24 ; v1(72.432,10.023) 72.432,10.032 72.536,10.136 72.861,10.136 72.95,10.225 D10.1@72.95,10.37 ; D10.1@72.95,10.375 72.994,10.419 72.994,10.712 73.016,10.734 73.016,11.014 72.994,11.036 72.994,11.091 72.955,11.13 72.95,11.13 D10.10@72.95,11.375 72.95,11.94 C153.2@73.35,12.34
  Bottom w0.132: v1(71.811,5.225) 71.916,5.329 71.916,6.912 72.093,7.089 72.093,9.541 72.414,9.862 72.414,10.014 72.423,10.023 v1(72.432,10.023)
SS3_2_TX_P: C152.2 D10.2 D10.9 J19.B2 | length 9
  Top w0.132: J19.B2@72.35,6.24 72.35,5.824 72.284,5.758 72.284,5.329 v1(72.389,5.225) ; v1(72.825,9.6) 72.95,9.6 73.45,10.1 D10.2@73.45,10.375 73.45,10.62 73.445,10.62 73.406,10.659 73.406,10.714 73.384,10.736 73.384,11.014 73.406,11.036 73.406,11.091 73.445,11.13 73.45,11.13 D10.9@73.45,11.375 73.45,11.6 74,12.15 C152.2@74.05,12.15
  Bottom w0.132: v1(72.389,5.225) 72.284,5.329 72.284,6.759 72.461,6.936 72.461,9.388 72.612,9.539 72.764,9.539 v1(72.825,9.6)
SS_1_TX_N: C151.1 U17.7 | length 3.7
  Bottom w0.132: C151.1@67.85,13.61 68.185,13.275 68.3,13.275 68.438,13.413 68.438,13.663 68.5,13.725 68.7,13.725 68.775,13.65 68.775,13.425 68.854,13.346 69.004,13.346 69.075,13.416 69.075,13.625 69.175,13.725 69.325,13.725 69.463,13.587 69.463,13.279 69.529,13.213 69.837,13.213 69.925,13.125 U17.7@70.075,13.125
SS_1_TX_P: C150.1 U17.8 | length 3.7
  Bottom w0.132: C150.1@66.825,13.61 67.318,14.103 69.468,14.103 70.046,13.525 U17.8@70.075,13.525
SS_2_TX_N: C153.1 U17.6 | length 10.2
  Top w0.132: v1(72.825,14.575) 73.35,14.05 C153.1@73.35,13.26
  Signal_4 w0.157: v1(69.2,12.95) 69.184,12.95 68.753,12.519 68.397,12.519 68.144,12.772 68.144,13.194 68.207,13.257 68.207,13.703 68.647,14.143 69.175,14.143 69.193,14.143 ccw(c69.193,14.304) 69.354,14.304 ; 69.354,14.305 cw(c69.515,14.305) 69.515,14.466 69.55,14.466 cw(c69.55,14.305) 69.711,14.305 ; 69.711,14.304 ccw(c69.872,14.304) 69.872,14.143 70.05,14.143 72.393,14.143 v1(72.825,14.575)
  Bottom w0.132: v1(69.2,12.95) 69.359,12.791 70.009,12.791 70.041,12.759 70.091,12.759 70.125,12.725 U17.6@70.125,12.675
SS_2_TX_P: C152.1 U17.5 | length 10.2
  Top w0.132: v1(73.779,14.501) 73.824,14.501 74.375,13.95 C152.1@74.375,13.26
  Signal_4 w0.157: v1(68.575,12.95) 68.575,13.55 68.8,13.775 73,13.775 73.726,14.501 v1(73.779,14.501)
  Bottom w0.132: v1(68.575,12.95) 69.102,12.423 69.856,12.423 69.972,12.307 70.332,12.307 70.525,12.5 U17.5@70.525,12.675
SWD_CLK/PWR_IO: CAD2.4 J9.4 R13.2 R15.1 U1.AN24 | length 103.9
  Top w0.127: R13.2@14.6,26.3 R15.1@15.54,26.3 15.54,26.74 15.775,26.975 v1(16.125,26.975) ; v1(14.7,58.8) 14.7,59.35 16.02,60.67 J9.4@16.832,60.67 ; v1(46.775,28.725) 48.085,28.725 U1.AN24@48.43,29.07
  Signal_4 w0.142: v1(14.7,58.8) 14.76,58.8 15.237,59.277 21.775,59.277 22.773,60.275 v1(23.6,60.275)
  Signal_7 w0.142: v1(23.6,60.275) 23.88,59.995 23.88,52.48 22.574,51.174 21.372,51.174 21.15,50.952 20.623,50.952 19.934,50.263 17.665,50.263 16.963,49.562 16.963,45.736 16.375,45.148 16.375,43.798 17.398,42.775 17.398,36.575 18.25,35.723 18.25,33.6 17.348,32.698 17.348,28.35 16.926,27.928 16.803,27.928 16.125,27.25 v1(16.125,26.975) 16.125,26.925 16.7,26.35 17.575,26.35 18.05,25.875 18.05,23.925 19.175,22.8 19.525,22.45 21.325,22.45 23.5,20.275 23.5,20.263 24.188,19.575 27.125,19.575 27.725,18.975 27.725,18.5 27.95,18.275 28.65,18.275 29.65,19.275 31.603,19.275 32.081,18.797 34.122,18.797 34.825,19.5 34.825,20.5 34.329,20.996 34.329,24.279 35.975,25.925 35.975,27.6 37.325,28.95 38.775,28.95 39.5,29.675 44.35,29.675 44.725,29.3 46.2,29.3 v1(46.775,28.725)
  Bottom w0.127: v1(14.7,58.8) 14.793,58.8 15.4,58.193 CAD2.4@15.4,58.16
SWD_DIO: CAD2.2 J9.2 U1.AN26 | length 70.4
  Top w0.127: J9.2@16.832,61.94 17.86,61.94 18.234,61.566 18.234,61.302 18.65,60.887 v1(18.65,60.575) ; v1(47.81,25.92) 47.82,25.92 U1.AN26@48.43,26.53
  Signal_4 w0.142: v1(18.65,60.575) 19.769,60.575 22.29,63.096 23.677,63.096 24.371,62.402 25.577,62.402 26.05,62.875 28.975,62.875 v1(29.55,62.3)
  Signal_7 w0.142: v1(29.55,62.3) 29.55,62.25 30.719,61.081 30.719,58.988 30.575,58.844 30.575,58.8 29.825,58.05 29.825,54.121 36.475,47.471 36.935,47.471 38.156,46.25 40.171,46.25 43.941,42.48 43.941,41.279 46.16,39.06 47.825,39.06 48.552,38.333 48.552,31.548 49.65,30.45 49.65,29.725 50.773,28.602 50.773,26.913 50.343,26.482 48.282,26.482 47.81,26.01 v1(47.81,25.92)
  Bottom w0.127: CAD2.2@15.4,60.7 15.463,60.763 18.462,60.763 v1(18.65,60.575)
SYS_RESET: CAD2.10 J9.10 J20.39 R17.1 SW2.3 SW2.4 U1.AN25 | length 128.1
  Top w0.127: J20.39@4,12.06 5.404,13.464 5.404,15.254 5.945,15.795 12.217,15.795 18.056,21.634 18.672,21.634 18.853,21.816 19.728,21.816 21.275,23.362 v1(21.275,23.375) 21.275,23.814 21.711,24.25 SW2.4@22.35,24.25 SW2.3@28.15,24.25 ; J9.10@16.832,56.86 18.365,56.86 18.409,56.816 18.409,55.516 18.525,55.4 v1(18.6,55.4) ; v1(47.81,27.19) 47.82,27.19 U1.AN25@48.43,27.8
  Signal_3 w0.142: v1(22.675,27.5) 23.678,27.5 24.603,26.575 24.603,25.205 23.122,23.723 23.025,23.723 22.777,23.475 22.777,21.725 v1(22.876,21.626)
  Signal_8 w0.142: v1(18.6,55.4) 18.596,55.4 14.883,51.687 14.883,40.067 16.173,38.777 16.173,36.134 15.518,35.479 15.518,34.463 15.103,34.047 15.103,33.601 15.35,33.354 15.509,33.354 15.963,32.899 15.963,32.877 16.527,32.313 16.563,32.313 19.059,29.818 19.059,29.036 20.589,27.506 22.669,27.506 v1(22.675,27.5) 29.85,27.5 32.75,24.6 34.038,24.6 35.052,25.613 35.563,25.613 36.106,26.156 36.106,27.607 38.125,29.626 38.125,29.798 38.677,30.35 40.7,30.35 41.475,31.125 42.819,31.125 43.12,30.824 45.896,30.824 46.144,30.576 46.144,28.758 47.712,27.19 v1(47.81,27.19)
  Bottom w0.127: CAD2.10@14.13,61.97 12.444,60.284 12.444,54.468 12.688,54.224 13.032,54.224 13.488,54.68 16.17,54.68 16.89,55.4 v1(18.6,55.4) ; v1(21.275,23.375) 22.23,22.42 R17.1@22.23,21.5 22.38,21.65 22.404,21.626 v1(22.876,21.626)
TCGND: J19.MT1 J19.MT2 J19.MT3 J19.MT4 R214.1 | length 3.2
  Top w0.4: R214.1@65.3,10.15 65.3,9.504 65.78,9.024 J19.MT1@65.78,7.13
UART0_CTS_B: J27.20 U1.M29 | length 87.7
  Top w0.127: v1(74.153,20.65) 74.153,20.922 75.1,21.869 U1.M29@75.1,22.72
  Signal_8 w0.142: J27.20@6.56,37.46 J27.20@6.57,37.47 ; J27.20@6.575,37.465 7.61,38.5 8.684,38.5 8.686,38.501 9.781,38.501 10.603,37.68 10.603,31.921 11.248,31.275 11.248,29.041 11.922,28.367 11.922,27.846 11.902,27.827 11.902,27.273 13.779,25.396 15.072,25.396 15.125,25.449 16.649,25.449 16.923,25.175 16.923,25.102 19.358,22.667 19.358,22.663 22.246,19.775 25.979,19.775 26.03,19.827 26.5,19.827 26.748,20.075 26.748,20.148 27.134,20.535 27.264,20.535 27.365,20.434 27.938,20.434 28.039,20.535 33.502,20.535 33.59,20.623 34.477,20.623 36.306,18.794 40.106,18.794 41.012,19.7 43.15,19.7 43.6,19.25 44.95,19.25 45.225,18.975 49.005,18.975 49.688,19.658 51.596,19.658 52.811,20.872 58.172,20.872 58.699,21.399 64.624,21.399 65.332,22.107 72.891,22.107 73.351,21.647 73.351,21.366 73.804,20.913 74.037,20.913 74.153,20.797 v1(74.153,20.65)
UART0_RTS_B: J27.18 U1.N29 | length 85.7
  Top w0.127: U1.N29@73.83,22.72 73.825,22.715 73.98,22.56 v1(73.98,21.336)
  Signal_8 w0.142: J27.18@6.56,40 7.791,38.769 8.573,38.769 8.574,38.771 9.893,38.771 10.872,37.792 10.872,32.032 11.517,31.387 11.517,29.152 12.498,28.171 13.844,28.171 13.852,28.163 14.025,28.163 14.802,27.387 14.802,26.85 15.68,25.971 17.454,25.971 17.671,25.754 17.671,24.734 19.627,22.779 19.627,22.775 21.598,20.804 25.648,20.804 25.825,20.627 26.103,20.627 26.15,20.673 26.221,20.673 26.352,20.804 27.375,20.804 27.476,20.703 27.827,20.703 27.928,20.804 33.39,20.804 33.479,20.892 34.588,20.892 36.417,19.063 39.994,19.063 40.981,20.05 43.225,20.05 43.75,19.525 45.216,19.525 45.623,19.933 47.384,19.933 47.8,20.349 51.906,20.349 52.699,21.142 57.942,21.142 58.468,21.668 64.493,21.668 65.202,22.377 73.003,22.377 73.83,21.549 73.825,21.544 73.98,21.39 v1(73.98,21.336)
UART0_RX: J27.19 U1.R1 | length 97.4
  Top w0.127: U1.R1@71.29,58.28 71.55,58.54 v1(71.55,59)
  Signal_3 w0.142: v1(5.525,59.275) 5.775,59.025 7.131,59.025 7.731,58.425 7.731,38.829 J27.19@9.1,37.46
  Signal_4 w0.142: v1(5.525,59.275) 5.925,58.875 10.05,58.875 11.122,57.803 12.925,57.803 13.885,56.842 13.894,56.851 21.828,56.851 22.71,55.969 31.164,55.969 32.032,56.837 33.635,56.837 34.737,57.938 35.437,57.938 39.006,61.508 42.287,61.508 42.939,62.16 51.981,62.16 52.564,61.576 52.564,61.572 54.011,60.125 55.45,60.125 55.744,59.831 56.294,59.831 57.376,58.749 57.884,58.749 58.06,58.925 62.352,58.925 62.925,59.498 63.275,59.498 64.197,58.577 69.736,58.577 70.485,59.326 71.224,59.326 v1(71.55,59)
UART0_TX: J27.17 U1.P1 | length 98
  Top w0.127: v1(72.35,59) 72.35,58.49 U1.P1@72.56,58.28
  Signal_3 w0.142: v1(6.9,61.675) 7.75,61.675 8,61.425 8,41.1 J27.17@9.1,40
  Signal_4 w0.142: v1(6.9,61.675) 7.423,62.198 9.375,62.198 10.277,61.297 10.277,60.603 10.603,60.277 11.05,60.277 11.072,60.299 11.246,60.299 13.595,57.95 18.125,57.95 18.446,58.271 21.449,58.271 22.819,56.902 26.72,56.902 27.193,57.375 33.248,57.375 37.075,61.202 37.075,61.636 38.265,62.826 39.427,62.826 39.43,62.823 56.177,62.823 57.175,61.825 57.175,60.95 57.675,60.45 60,60.45 60.413,60.037 65.1,60.037 65.557,59.58 67.411,59.58 67.931,60.1 68.475,60.1 68.643,59.932 68.643,59.762 69.13,59.275 70.053,59.275 70.323,59.545 70.323,59.55 70.368,59.595 71.755,59.595 v1(72.35,59)
UART3_RX: U4.3 U8.1 | length 11.7
  Bottom w0.127: U8.1@19.37,51.915 18.685,51.915 18.304,51.533 18.304,51.477 18.195,51.368 18.195,48.982 18.1,48.887 18.1,45.725 18.286,45.539 20.515,45.539 20.704,45.35 21.575,45.35 21.825,45.1 22.425,45.1 U4.3@22.45,45.125
UART3_TX: U5.3 U8.4 | length 3.6
  Bottom w0.127: U8.4@19.37,48.105 20.055,48.105 20.864,48.914 22.438,48.914 U5.3@22.575,49.05
USB_HUB_RESET_N: C83.2 R12.2 R137.1 U1.E17 U13.26 | length 116
  Top w0.127: U13.26@27.5,59.3 27.5,60.025 27.225,60.3 v1(27.05,60.3) 27.05,60.67 27.025,60.695 27.203,60.873 26.425,61.65 26.425,66.85 28,68.425 v1(28,69.2) ; U1.E17@83.99,37.96 84.6,37.35 v1(84.6,37.34)
  Signal_7 w0.142: v1(28,69.2) 28.15,69.2 28.89,69.94 48.05,69.94 48.612,69.379 59.898,69.379 59.916,69.361 65.72,69.361 65.79,69.431 66.81,69.431 66.862,69.379 68.195,69.379 68.224,69.408 85.05,69.408 90.9,63.558 90.9,62.275 89.112,60.487 89.112,59.153 88.95,58.991 88.95,58.747 88.958,58.74 88.958,53.55 88.95,53.542 88.95,53.454 90.372,52.032 90.372,42.165 89.856,41.65 87.5,41.65 86.568,40.718 86.568,39.832 84.6,37.865 v1(84.6,37.34)
  Bottom w0.127: v1@27.025,60.26 27.025,59.535 C83.2@27.05,59.51 ; R12.2@81.625,34.03 81.625,36.45 82,36.825 84.085,36.825 v1(84.6,37.34)
USB_OTG1_N: R240.1 R242.2 TP16.1 U1.A6 U13.30 | length 152.8
  Top w0.132: v1(24.95,57.925) 25.225,57.925 25.65,57.5 U13.30@26.2,57.5 ; U1.A6@89.07,51.93 89.07,51.589 89.18,51.479 89.84,51.479 90.52,52.159 90.52,52.425 90.52,52.442 ccw(c90.371,52.442) 90.371,52.591 90.04,52.591 cw(c90.04,52.74) 89.891,52.74 89.891,52.774 cw(c90.04,52.774) 90.04,52.923 90.371,52.923 ccw(c90.371,53.073) 90.52,53.073 90.52,53.1 90.52,55.279 90.026,55.773 90.003,55.796 89.952,55.745 v1(89.952,55.699)
  Signal_3 w0.157: v1(62.3,20.976) 62.404,20.872 63.625,20.872 63.643,20.872 ccw(c63.643,21.033) 63.804,21.033 63.804,21.377 cw(c63.965,21.377) 63.965,21.538 64,21.538 cw(c64,21.377) 64.161,21.377 64.161,21.033 ccw(c64.322,21.033) 64.322,20.872 64.425,20.872 69.899,20.872 71.802,18.969 73.346,18.969 74.712,20.335 81.835,20.335 82.475,20.975 83.159,20.975 83.831,21.647 83.831,22.003 83.829,22.005 83.829,47.956 84.197,48.325 84.741,48.325 85.892,49.476 85.892,50.752 87.64,52.5 89.44,52.5 90.32,53.38 90.32,55.479 90.026,55.773 90.003,55.796 89.952,55.745 v1(89.952,55.699)
  Signal_4 w0.157: v1(24.95,57.925) 24.85,57.825 24.225,57.825 23.95,58.1 23.95,58.525 24.25,58.825 25.128,58.825 25.244,58.709 26.075,58.709 26.203,58.709 cw(c26.203,58.548) 26.364,58.548 26.364,57.99 ccw(c26.525,57.99) 26.525,57.829 26.56,57.829 ccw(c26.56,57.99) 26.721,57.99 26.721,58.548 cw(c26.882,58.548) 26.882,58.709 26.9,58.709 28.689,58.709 28.906,58.492 33.5,58.492 36.45,61.442 36.45,63.15 37.507,64.207 57.347,64.207 58.676,62.878 58.676,62.328 59.454,61.55 62.825,61.55 63.4,60.975 87.95,60.975 89.028,59.897 89.028,56.771 89.952,55.847 v1(89.952,55.699)
  Bottom w0.132: TP16.1@25.325,58.6 24.95,58.225 v1(24.95,57.925) 25.215,57.925 R240.1@25.7,57.44 ; R242.2@61.455,21.2 61.783,20.872 62.196,20.872 v1(62.3,20.976)
USB_OTG1_P: R241.1 R243.2 TP15.1 U1.A7 U13.31 | length 153
  Top w0.132: v1(24.95,57.325) 25.275,57.325 25.6,57 U13.31@26.2,57 ; U1.A7@89.07,50.66 89.07,51.001 89.18,51.111 89.993,51.111 90.888,52.007 90.888,55.432 90.264,56.056 v1(90.264,56.204)
  Signal_3 w0.157: v1(62.3,20.399) 62.404,20.503 69.747,20.503 71.65,18.6 73.498,18.6 74.865,19.967 82.06,19.967 82.7,20.607 83.407,20.607 84.115,21.315 84.115,22.121 84.113,22.123 84.113,47.72 84.35,47.957 85.082,47.957 86.26,49.135 86.26,50.599 87.793,52.132 89.593,52.132 90.688,53.227 90.688,55.632 90.264,56.056 v1(90.264,56.204)
  Signal_4 w0.157: v1(24.95,57.325) 24.871,57.325 24.755,57.441 23.959,57.441 23.625,57.775 23.625,58.825 23.969,59.169 25.304,59.169 25.397,59.077 28.842,59.077 29.094,58.825 33.312,58.825 36.082,61.594 36.082,63.303 37.354,64.575 57.5,64.575 59.044,63.031 59.044,62.481 59.625,61.9 62.996,61.9 63.596,61.3 88.1,61.3 89.397,60.003 89.397,56.923 90.116,56.204 v1(90.264,56.204)
  Bottom w0.132: TP15.1@23.675,58.375 24.1,57.95 R241.1@24.1,57.44 24.215,57.325 v1(24.95,57.325) ; R243.2@61.455,20.175 61.783,20.503 62.196,20.503 v1(62.3,20.399)
USB_OTG2_ID: J28.4 U1.C10 | length 73.7
  Top w0.127: U1.C10@86.53,46.85 87.14,47.46 v1(87.15,47.46)
  Signal_4 w0.142: v1(55.35,5.375) 55.35,5.4 55.9,5.95 59.275,5.95 59.725,5.5 66.15,5.5 68.75,8.1 72.7,8.1 73.902,9.302 73.925,9.302 74.173,9.55 74.173,11.948 75.875,13.65 82.425,13.65 85.875,17.1 85.875,18.875 86.113,19.113 86.687,19.113 89.848,22.275 89.848,26.075 89.144,26.779 89.144,44.736 88.589,45.291 87.169,45.291 86.7,45.76 86.7,47.01 v1(87.15,47.46)
  Bottom w0.127: J28.4@55.35,4.35 v1(55.35,5.375)
USB_OTG2_N: D1.2 D1.9 J19.A7 J19.B7 L38.1 R238.2 U1.A8 | length 97.7
  Top w0.132: v1(66.003,13.876) 66.799,13.876 67.182,13.493 67.993,13.493 68.325,13.825 69.521,13.825 70.334,13.012 70.334,11.782 70.4,11.716 D1.9@70.4,11.35 D1.2@70.4,10.35 70.4,9.884 70.334,9.818 70.334,9.284 70.284,9.234 70.284,8.909 v1(70.45,8.743) 70.6,8.593 J19.A7@70.6,7.94 ; v1(69.475,7.05) 69.85,6.675 J19.B7@69.85,6.24
  Top w0.157: U1.A8@89.07,49.39 89.07,49.064 89.3,48.834 89.874,48.834 90.578,49.537 91.317,49.537 91.68,49.9 v1(91.68,50.06)
  Signal_3 w0.157: v1(66.003,13.876) 66.003,13.822 66.266,13.559 67.978,13.559 68.489,14.07 73.957,14.07 73.959,14.072 74.078,14.072 74.8,13.35 80.825,13.35 85.569,18.094 85.569,18.575 86.141,19.147 86.722,19.147 88.959,21.384 91.297,21.384 91.931,22.018 91.931,27.044 91.55,27.425 91.55,37.05 92.807,38.307 92.807,41.568 91.55,42.825 v1@91.55,50.06
  Signal_4 w0.157: v1(57.318,8.875) 57.318,8.796 57.159,8.636 57.159,8.425 57.251,8.333 57.905,8.333 58.25,8.678 58.25,8.8 58,9.05 58,9.225 58.1,9.325 58.325,9.325 58.55,9.1 58.672,9.1 59.047,9.475 59.779,9.475 61.479,11.175 64.45,11.175 65.694,12.419 65.694,13.567 v1(66.003,13.876)
  Bottom w0.132: v1(57.318,8.875) 57.159,8.716 57.159,8.357 57.375,8.141 L38.1@57.375,7.625 ; v1(69.475,7.05) 69.725,7.05 70.2,6.575 70.625,6.575 70.925,6.875 70.925,7.734 70.284,8.375 70.284,8.577 v1(70.45,8.743) ; R238.2@90.605,53.77 90.881,53.494 90.881,51.778 91.985,50.674 91.985,50.215 91.83,50.06 v1(91.68,50.06)
USB_OTG2_P: D1.1 D1.10 J19.A6 J19.B6 L38.4 R239.2 U1.A9 | length 96.5
  Top w0.132: v1(66.125,13.025) 66.95,13.025 67.05,13.125 67.4,13.125 67.5,13.025 67.5,12.85 67.6,12.75 67.75,12.75 67.85,12.85 67.85,13.05 67.925,13.125 68.146,13.125 68.478,13.457 69.368,13.457 69.966,12.859 69.966,12.7 69.8,12.534 69.8,12.241 69.966,12.075 69.966,11.782 69.9,11.716 D1.10@69.9,11.35 D1.1@69.9,10.345 69.9,9.879 69.966,9.813 69.966,9.437 69.916,9.387 69.916,8.916 v1(69.75,8.75) 69.6,8.6 J19.A6@69.6,7.94 ; v1(70.05,7.325) 70.35,7.025 J19.B6@70.35,6.24
  Top w0.157: U1.A9@89.07,48.12 89.07,48.446 89.178,48.554 89.182,48.549 89.992,48.549 90.696,49.253 91.435,49.253 91.782,49.6 v1(92.04,49.6)
  Signal_3 w0.157: v1(66.125,13.025) 66.15,13.025 66.316,13.191 68.131,13.191 68.69,13.75 73.879,13.75 74.647,12.982 81.082,12.982 86.019,17.919 86.019,18.578 86.272,18.831 87.006,18.831 89.275,21.1 91.499,21.1 92.299,21.9 92.299,27.197 91.918,27.578 91.918,36.897 93.175,38.154 93.175,41.721 91.918,42.978 v1@91.918,49.6
  Signal_4 w0.157: v1(56.631,8.875) 56.631,8.796 56.791,8.636 56.791,8.273 57.099,7.965 58.057,7.965 59.193,9.1 59.925,9.1 61.65,10.825 64.6,10.825 66.125,12.35 v1(66.125,13.025)
  Bottom w0.132: L38.4@56.575,7.625 56.575,8.141 56.791,8.357 56.791,8.716 v1(56.631,8.875) ; v1(69.75,8.75) 69.916,8.584 69.916,8.222 70.557,7.582 70.557,7.028 70.472,6.943 70.353,6.943 70.05,7.246 v1(70.05,7.325) ; R239.2@91.525,53.77 91.249,53.494 91.249,51.931 92.353,50.827 92.353,50.063 92.04,49.75 v1(92.04,49.6)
